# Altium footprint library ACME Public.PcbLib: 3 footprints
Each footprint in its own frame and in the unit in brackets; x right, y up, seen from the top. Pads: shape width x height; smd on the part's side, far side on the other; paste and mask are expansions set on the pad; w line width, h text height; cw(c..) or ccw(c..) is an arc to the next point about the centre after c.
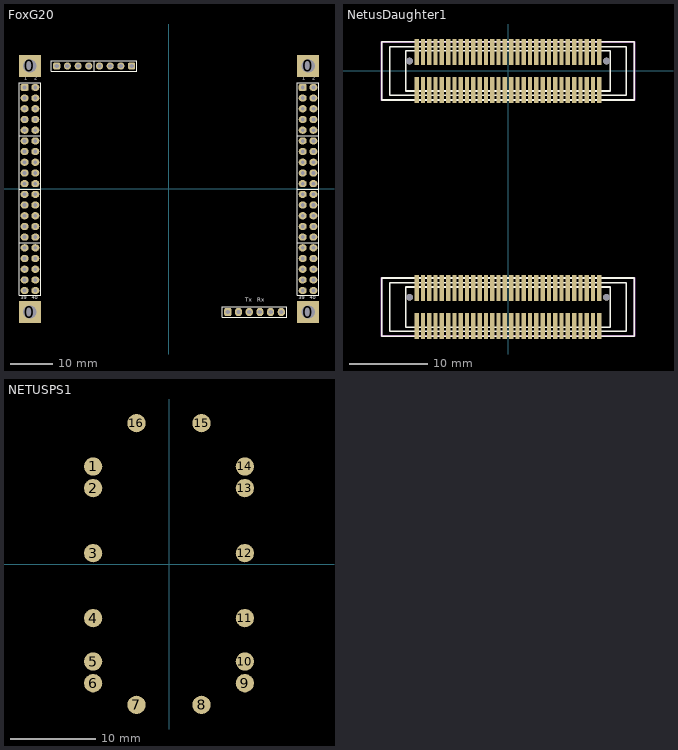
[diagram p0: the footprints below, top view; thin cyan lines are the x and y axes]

## FoxG20 [mm] "Connector; Header; 20x2 Position"
height 2.67
pads (98):
  rect 5.2x5.2 / inner rect 3.8x3.8 / far side rect 5.2x5.2 hole 3.2: 0(-33,-29.25) 0(-33,29.17) 0(33.04,-29.25) 0(33.04,29.17)
  rrect50% 1.9x1.7 hole 0.9: 1(-34.27,24.09) 41(31.77,24.09)
  oval 1.9x1.7 hole 0.9: 2(-31.73,24.09) 3(-34.27,21.55) 4(-31.73,21.55) 5(-34.27,19.01) 6(-31.73,19.01) 7(-34.27,16.47) 8(-31.73,16.47) 9(-34.27,13.93) 10(-31.73,13.93) 11(-34.27,11.39) 12(-31.73,11.39) 13(-34.27,8.85) 14(-31.73,8.85) 15(-34.27,6.31) 16(-31.73,6.31) 17(-34.27,3.77) 18(-31.73,3.77) 19(-34.27,1.23) 20(-31.73,1.23) 21(-34.27,-1.31) 22(-31.73,-1.31) 23(-34.27,-3.85) 24(-31.73,-3.85) 25(-34.27,-6.39) 26(-31.73,-6.39) 27(-34.27,-8.93) 28(-31.73,-8.93) 29(-34.27,-11.47) 30(-31.73,-11.47) 31(-34.27,-14.01) 32(-31.73,-14.01) 33(-34.27,-16.55) 34(-31.73,-16.55) 35(-34.27,-19.09) 36(-31.73,-19.09) 37(-34.27,-21.63) 38(-31.73,-21.63) 39(-34.27,-24.17) 40(-31.73,-24.17) 42(34.31,24.09) 43(31.77,21.55) 44(34.31,21.55) 45(31.77,19.01) 46(34.31,19.01) 47(31.77,16.47) 48(34.31,16.47) 49(31.77,13.93) 50(34.31,13.93) 51(31.77,11.39) 52(34.31,11.39) 53(31.77,8.85) 54(34.31,8.85) 55(31.77,6.31) 56(34.31,6.31) 57(31.77,3.77) 58(34.31,3.77) 59(31.77,1.23) 60(34.31,1.23) 61(31.77,-1.31) 62(34.31,-1.31) 63(31.77,-3.85) 64(34.31,-3.85) 65(31.77,-6.39) 66(34.31,-6.39) 67(31.77,-8.93) 68(34.31,-8.93) 69(31.77,-11.47) 70(34.31,-11.47) 71(31.77,-14.01) 72(34.31,-14.01) 73(31.77,-16.55) 74(34.31,-16.55) 75(31.77,-19.09) 76(34.31,-19.09) 77(31.77,-21.63) 78(34.31,-21.63) 79(31.77,-24.17) 80(34.31,-24.17)
  rrect50% 1.7x1.7 hole 1.05: 81(-26.65,29.17) 88(-8.87,29.17)
  round 1.7 hole 1.05: 82(-24.11,29.17) 83(-21.57,29.17) 84(-19.03,29.17) 85(-16.49,29.17) 86(-13.95,29.17) 87(-11.41,29.17)
  rrect50% 1.7x2 hole 1.05: 89(13.99,-29.25)
  oval 1.7x2 hole 1.05: 90(16.53,-29.25) 91(19.07,-29.25) 92(21.61,-29.25) 93(24.15,-29.25) 94(26.69,-29.25)
Top Overlay:
  lines w0.2: -35.47,-12.745 -30.47,-12.745 ; -35.47,-0.045 -30.46,-0.045 ; -35.47,12.655 -30.453,12.655 ; 30.57,-12.745 35.57,-12.745 ; 30.57,-0.045 35.57,-0.045 ; 30.57,12.655 35.57,12.655 ; -17.76,27.9 -17.76,30.44 ; -17.76,27.9 -7.6,27.9 -7.6,30.44 -17.76,30.44 ; -17.76,27.9 -27.92,27.9 -27.92,30.44 -17.76,30.44 ; -17.76,27.9 -17.76,30.44 ; -35.54,-25.31 -35.54,25.24 -30.46,25.24 -30.46,-25.31 -35.54,-25.31 ; 12.72,-30.52 12.72,-27.98 27.96,-27.98 27.96,-30.52 12.72,-30.52 ; 30.5,-25.31 30.5,25.24 35.58,25.24 35.58,-25.31 30.5,-25.31
  text "Rx" at 20.962,-27.16 h1.7
  text "Tx" at 18.152,-27.13 h1.7
  text "39" at 30.817,-26.57 h1.5
  text "40" at 33.421,-26.583 h1.5
  text "1" at 31.706,25.551 h1.5
  text "2" at 34.056,25.551 h1.5
  text "39" at -35.223,-26.57 h1.5
  text "40" at -32.619,-26.583 h1.5
  text "1" at -34.334,25.551 h1.5
  text "2" at -31.984,25.551 h1.5
Bottom Overlay:
  lines w0.2: -35.47,-12.745 -30.47,-12.745 ; -35.47,-0.045 -30.47,-0.045 ; -35.47,12.655 -30.47,12.655 ; 30.57,-12.745 35.57,-12.745 ; 30.57,-0.045 35.57,-0.045 ; 30.57,12.655 35.57,12.655 ; -35.54,-25.31 -35.54,25.24 -30.46,25.24 -30.46,-25.31 -35.54,-25.31 ; 12.72,-30.52 27.96,-30.52 27.96,-27.98 12.72,-27.98 12.72,-30.52 ; 30.5,-25.31 30.5,25.24 35.58,25.24 35.58,-25.31 30.5,-25.31
  text "6" at 27.032,-26.97 h1.5
  text "5" at 24.482,-26.97 h1.5
  text "Rx" at 22.052,-26.97 h1.5
  text "Tx" at 19.742,-26.97 h1.5
  text "2" at 16.932,-26.97 h1.5
  text "1" at 14.332,-26.97 h1.5
  text "39" at 32.167,-26.57 h1.5
  text "40" at 34.771,-26.583 h1.5
  text "2" at 34.72,25.565 h1.5
  text "1" at 32.095,25.565 h1.5
  text "39" at -33.873,-26.57 h1.5
  text "40" at -31.269,-26.583 h1.5
  text "2" at -31.32,25.565 h1.5
  text "1" at -33.945,25.565 h1.5
3D body: height 21.57, standoff 2.78, extent -36.068,-34.1 36.068,37.512
3D body: height 0.1, standoff 0, extent -12.795,29.02 -12.52,29.22
3D body: height 0.1, standoff 0, extent -23,29.12 -22.725,29.32

## NetusDaughter1 [mm] "PAD for Netus_Core_1 Board to be used in daughter boards"
height 3.6
pads (124):
  round 0.85 hole 0.85 paste+0 mask+0: 0(-12.5,-28.75) 0(-12.5,1.25) 0(12.5,-28.75) 0(12.5,1.25)
  rect 0.55x3.3 smd: 1(-11.6,-32.4) 1(-11.6,-2.4) 2(-11.6,-27.6) 2(-11.6,2.4) 3(-10.8,-32.4) 3(-10.8,-2.4) 4(-10.8,-27.6) 4(-10.8,2.4) 5(-10,-32.4) 5(-10,-2.4) 6(-10,-27.6) 6(-10,2.4) 7(-9.2,-32.4) 7(-9.2,-2.4) 8(-9.2,-27.6) 8(-9.2,2.4) 9(-8.4,-32.4) 9(-8.4,-2.4) 10(-8.4,-27.6) 10(-8.4,2.4) 11(-7.6,-32.4) 11(-7.6,-2.4) 12(-7.6,-27.6) 12(-7.6,2.4) 13(-6.8,-32.4) 13(-6.8,-2.4) 14(-6.8,-27.6) 14(-6.8,2.4) 15(-6,-32.4) 15(-6,-2.4) 16(-6,-27.6) 16(-6,2.4) 17(-5.2,-32.4) 17(-5.2,-2.4) 18(-5.2,-27.6) 18(-5.2,2.4) 19(-4.4,-32.4) 19(-4.4,-2.4) 20(-4.4,-27.6) 20(-4.4,2.4) 21(-3.6,-32.4) 21(-3.6,-2.4) 22(-3.6,-27.6) 22(-3.6,2.4) 23(-2.8,-32.4) 23(-2.8,-2.4) 24(-2.8,-27.6) 24(-2.8,2.4) 25(-2,-32.4) 25(-2,-2.4) 26(-2,-27.6) 26(-2,2.4) 27(-1.2,-32.4) 27(-1.2,-2.4) 28(-1.2,-27.6) 28(-1.2,2.4) 29(-0.4,-32.4) 29(-0.4,-2.4) 30(-0.4,-27.6) 30(-0.4,2.4) 31(0.4,-32.4) 31(0.4,-2.4) 32(0.4,-27.6) 32(0.4,2.4) 33(1.2,-32.4) 33(1.2,-2.4) 34(1.2,-27.6) 34(1.2,2.4) 35(2,-32.4) 35(2,-2.4) 36(2,-27.6) 36(2,2.4) 37(2.8,-32.4) 37(2.8,-2.4) 38(2.8,-27.6) 38(2.8,2.4) 39(3.6,-32.4) 39(3.6,-2.4) 40(3.6,-27.6) 40(3.6,2.4) 41(4.4,-32.4) 41(4.4,-2.4) 42(4.4,-27.6) 42(4.4,2.4) 43(5.2,-32.4) 43(5.2,-2.4) 44(5.2,-27.6) 44(5.2,2.4) 45(6,-32.4) 45(6,-2.4) 46(6,-27.6) 46(6,2.4) 47(6.8,-32.4) 47(6.8,-2.4) 48(6.8,-27.6) 48(6.8,2.4) 49(7.6,-32.4) 49(7.6,-2.4) 50(7.6,-27.6) 50(7.6,2.4) 51(8.4,-32.4) 51(8.4,-2.4) 52(8.4,-27.6) 52(8.4,2.4) 53(9.2,-32.4) 53(9.2,-2.4) 54(9.2,-27.6) 54(9.2,2.4) 55(10,-32.4) 55(10,-2.4) 56(10,-27.6) 56(10,2.4) 57(10.8,-32.4) 57(10.8,-2.4) 58(10.8,-27.6) 58(10.8,2.4) 59(11.6,-32.4) 59(11.6,-2.4) 60(11.6,-27.6) 60(11.6,2.4)
Top Overlay:
  lines w0.2: -16.05,-33.7 16.05,-33.7 16.05,-26.3 -16.05,-26.3 -16.05,-33.7 ; -16.05,-3.7 -16.05,3.7 16.05,3.7 16.05,-3.7 -16.05,-3.7 ; -15,-33.075 15,-33.075 15,-26.925 -15,-26.925 -15,-33.075 ; -15,-3.075 -15,3.075 15,3.075 15,-3.075 -15,-3.075 ; -13,-32.55 13,-32.55 13,-27.45 -13,-27.45 -13,-32.55 ; -13,-2.55 -13,2.55 13,2.55 13,-2.55 -13,-2.55
Mechanical 13:
  lines w0.254: -16.05,-33.7 -16.05,-26.3 16.05,-26.3 16.05,-33.7 -16.05,-33.7 ; -16.05,-3.7 16.05,-3.7 16.05,3.7 -16.05,3.7 -16.05,-3.7
3D body: height 3.5, standoff 0, extent -13,-32.525 13.025,-27.475
3D body: height 3.5, standoff 0, extent -13,-2.525 13.025,2.525

## NETUSPS1 [mm]
pads (16):
  round 2.14 smd mask+0.07: 1(-8.89,11.43) 2(-8.89,8.89) 3(-8.89,1.27) 4(-8.89,-6.35) 5(-8.89,-11.43) 6(-8.89,-13.97) 7(-3.81,-16.51) 8(3.81,-16.51) 9(8.89,-13.97) 10(8.89,-11.43) 11(8.89,-6.35) 12(8.89,1.27) 13(8.89,8.89) 14(8.89,11.43) 15(3.81,16.51) 16(-3.81,16.51)
3D body: height 3.51, standoff 0.08, extent -8.84,-16.445 8.935,16.575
